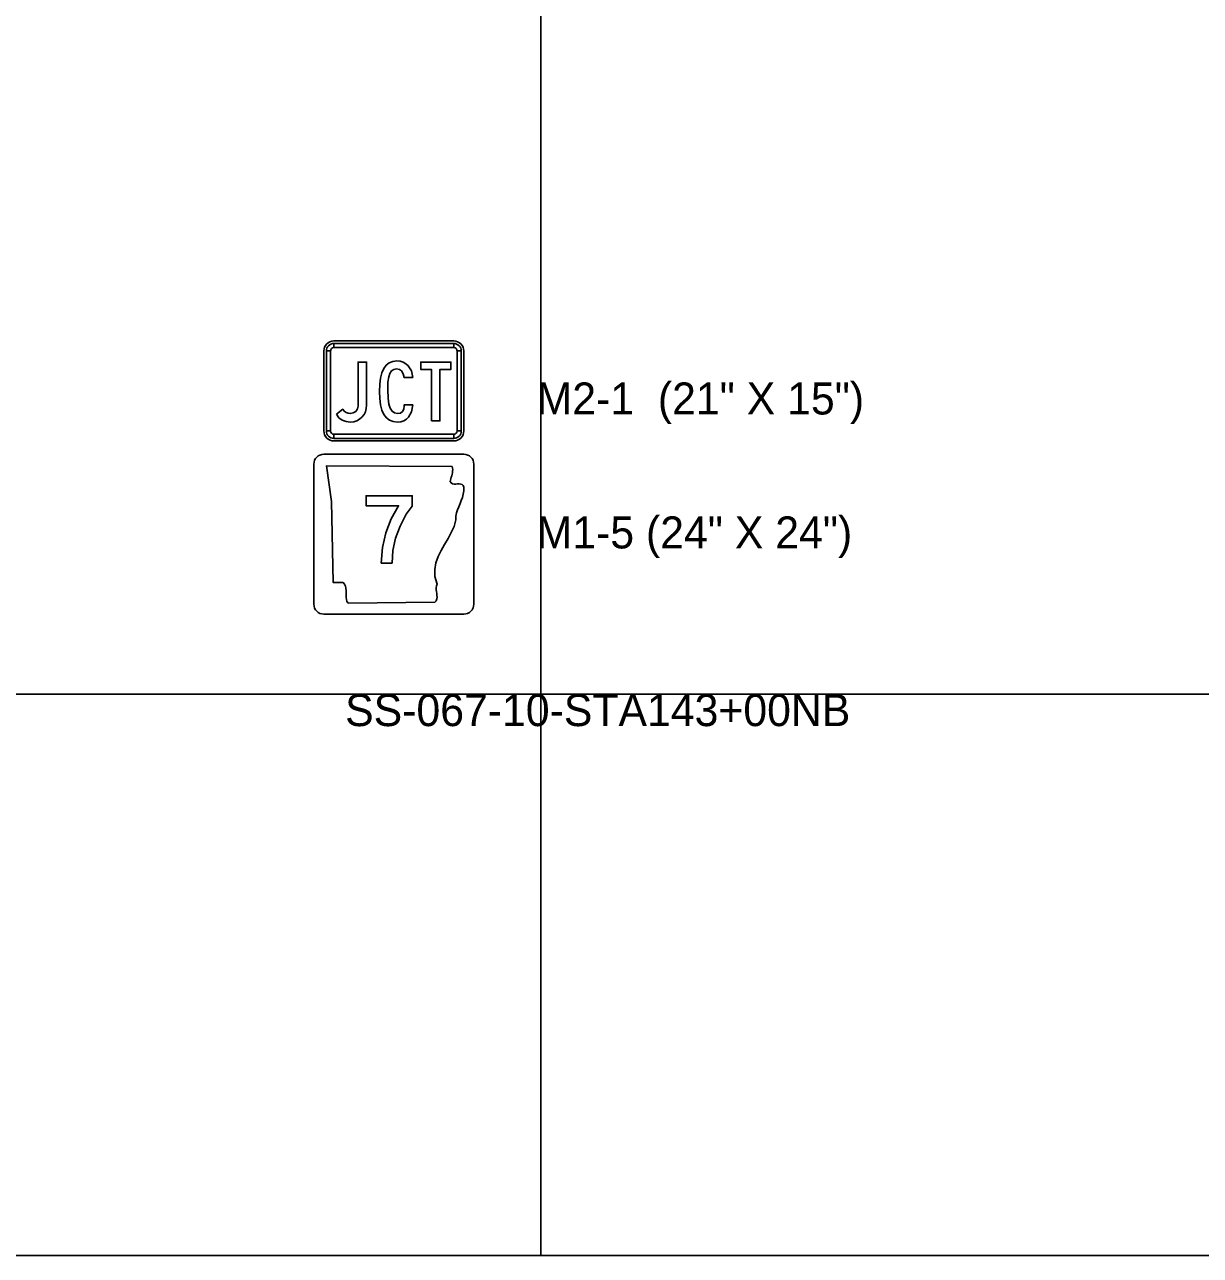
# Model space of a CAD drawing. Extents: x 1001568 to 1002149, y 1840825 to 1841423.
# Drawn here: x 1001929.19 to 1001943.9, y 1841248.13 to 1841263.52 of the extents above; entities that cross this region are included whole.
import ezdxf

# ---------------------------------------------------------------- set-up
doc = ezdxf.new("R2010")
doc.units = 0
for name, color, linetype in [('40', 7, 'Continuous'), ('R_No Plot', 7, 'Continuous'), ('SIGNS', 7, 'Continuous')]:
    doc.layers.add(name, color=color, linetype=linetype)

msp = doc.modelspace()

# ---------------------------------------------------------------- linework, layer by layer
at = {"layer": 'R_No Plot'}
for p, q in [((1001935.65, 1841310.667), (1001935.65, 1841248.127)), ((1001890.65, 1841255.146), (1001982.133, 1841255.146))]:
    msp.add_line(p, q, dxfattribs=at)
msp.add_lwpolyline([(1001886.411, 1841310.667), (1001964.232, 1841310.667), (1001964.232, 1841307.694), (1001968.454, 1841307.694), (1001968.454, 1841306.882), (1001982.133, 1841306.882), (1001982.133, 1841248.127), (1001886.411, 1841248.127)], close=True, dxfattribs=at)
at = {"layer": 'SIGNS'}
for p, q in [((1001933.06, 1841259.562), (1001934.56, 1841259.562)), ((1001933.06, 1841259.479), (1001933.06, 1841259.531)), ((1001934.56, 1841259.531), (1001934.56, 1841259.479)), ((1001932.935, 1841258.437), (1001932.935, 1841259.437)), ((1001932.966, 1841259.437), (1001933.018, 1841259.437)), ((1001934.601, 1841259.437), (1001934.654, 1841259.437)), ((1001934.685, 1841259.437), (1001934.685, 1841258.437)), ((1001933.018, 1841258.437), (1001932.966, 1841258.437)), ((1001933.06, 1841258.344), (1001933.06, 1841258.396)), ((1001934.56, 1841258.396), (1001934.56, 1841258.344)), ((1001934.654, 1841258.437), (1001934.601, 1841258.437)), ((1001934.56, 1841258.312), (1001933.06, 1841258.312)), ((1001934.685, 1841258.146), (1001932.935, 1841258.146)), ((1001932.81, 1841258.021), (1001932.81, 1841256.271)), ((1001934.81, 1841256.271), (1001934.81, 1841258.021)), ((1001932.81, 1841256.271), (1001932.81, 1841256.271)), ((1001932.935, 1841256.146), (1001934.685, 1841256.146))]:
    msp.add_line(p, q, dxfattribs=at)
for points in [[(1001934.56, 1841259.531), (1001933.06, 1841259.531), (1001933.06, 1841259.479), (1001934.56, 1841259.479), (1001934.56, 1841259.531), (1001934.56, 1841259.531)], [(1001932.966, 1841259.437), (1001932.966, 1841258.437), (1001933.018, 1841258.437), (1001933.018, 1841259.437), (1001932.966, 1841259.437), (1001932.966, 1841259.437)], [(1001934.047, 1841259.107), (1001934.029, 1841259.188), (1001933.99, 1841259.252), (1001933.961, 1841259.278), (1001933.927, 1841259.297), (1001933.889, 1841259.309), (1001933.846, 1841259.312), (1001933.796, 1841259.306), (1001933.752, 1841259.289), (1001933.715, 1841259.259), (1001933.685, 1841259.217), (1001933.661, 1841259.164), (1001933.645, 1841259.098), (1001933.634, 1841259.021), (1001933.631, 1841258.932), (1001933.635, 1841258.842), (1001933.645, 1841258.764), (1001933.662, 1841258.698), (1001933.687, 1841258.644), (1001933.718, 1841258.602), (1001933.756, 1841258.572), (1001933.801, 1841258.554), (1001933.854, 1841258.548), (1001933.896, 1841258.552), (1001933.934, 1841258.564), (1001933.967, 1841258.583), (1001933.995, 1841258.611), (1001934.031, 1841258.677), (1001934.047, 1841258.762), (1001933.939, 1841258.762), (1001933.94, 1841258.75), (1001933.936, 1841258.711), (1001933.92, 1841258.681), (1001933.894, 1841258.661), (1001933.857, 1841258.655), (1001933.82, 1841258.662), (1001933.789, 1841258.684), (1001933.765, 1841258.72), (1001933.749, 1841258.772), (1001933.738, 1841258.847), (1001933.735, 1841258.952), (1001933.737, 1841259.047), (1001933.746, 1841259.112), (1001933.761, 1841259.156), (1001933.782, 1841259.188), (1001933.81, 1841259.207), (1001933.844, 1841259.213), (1001933.88, 1841259.206), (1001933.908, 1841259.187), (1001933.928, 1841259.153), (1001933.939, 1841259.107)], [(1001934.654, 1841258.437), (1001934.654, 1841259.437), (1001934.601, 1841259.437), (1001934.601, 1841258.437), (1001934.654, 1841258.437), (1001934.654, 1841258.437)], [(1001933.091, 1841258.645), (1001933.122, 1841258.603), (1001933.165, 1841258.573), (1001933.213, 1841258.554), (1001933.266, 1841258.548), (1001933.308, 1841258.552), (1001933.346, 1841258.563), (1001933.38, 1841258.583), (1001933.411, 1841258.61), (1001933.437, 1841258.642), (1001933.455, 1841258.678), (1001933.466, 1841258.717), (1001933.469, 1841258.759), (1001933.469, 1841259.298), (1001933.363, 1841259.298), (1001933.363, 1841258.748), (1001933.355, 1841258.712), (1001933.334, 1841258.682), (1001933.303, 1841258.662), (1001933.266, 1841258.655), (1001933.237, 1841258.658), (1001933.212, 1841258.668), (1001933.19, 1841258.685), (1001933.172, 1841258.708)], [(1001934.28, 1841258.562), (1001934.387, 1841258.562), (1001934.387, 1841259.206), (1001934.524, 1841259.206), (1001934.524, 1841259.298), (1001934.146, 1841259.298), (1001934.146, 1841259.206), (1001934.28, 1841259.206)], [(1001933.06, 1841258.344), (1001934.56, 1841258.344), (1001934.56, 1841258.396), (1001933.06, 1841258.396), (1001933.06, 1841258.344), (1001933.06, 1841258.344)], [(1001934.54, 1841257.991), (1001934.544, 1841257.972), (1001934.546, 1841257.953), (1001934.545, 1841257.934), (1001934.543, 1841257.915), (1001934.539, 1841257.896), (1001934.534, 1841257.877), (1001934.529, 1841257.858), (1001934.523, 1841257.839), (1001934.518, 1841257.821), (1001934.513, 1841257.803), (1001934.527, 1841257.787), (1001934.544, 1841257.777), (1001934.564, 1841257.773), (1001934.585, 1841257.773), (1001934.606, 1841257.774), (1001934.627, 1841257.774), (1001934.646, 1841257.772), (1001934.663, 1841257.766), (1001934.676, 1841257.754), (1001934.684, 1841257.733), (1001934.685, 1841257.688), (1001934.679, 1841257.645), (1001934.668, 1841257.605), (1001934.654, 1841257.566), (1001934.638, 1841257.528), (1001934.622, 1841257.49), (1001934.607, 1841257.452), (1001934.595, 1841257.412), (1001934.587, 1841257.371), (1001934.585, 1841257.327), (1001934.563, 1841257.244), (1001934.529, 1841257.166), (1001934.488, 1841257.091), (1001934.444, 1841257.016), (1001934.401, 1841256.941), (1001934.363, 1841256.865), (1001934.335, 1841256.787), (1001934.321, 1841256.704), (1001934.324, 1841256.617), (1001934.35, 1841256.523), (1001934.342, 1841256.5), (1001934.34, 1841256.476), (1001934.34, 1841256.452), (1001934.343, 1841256.428), (1001934.347, 1841256.404), (1001934.349, 1841256.381), (1001934.35, 1841256.357), (1001934.347, 1841256.336), (1001934.338, 1841256.314), (1001934.323, 1841256.295), (1001933.239, 1841256.285), (1001933.224, 1841256.305), (1001933.216, 1841256.328), (1001933.212, 1841256.355), (1001933.212, 1841256.383), (1001933.213, 1841256.413), (1001933.213, 1841256.442), (1001933.211, 1841256.471), (1001933.205, 1841256.498), (1001933.194, 1841256.522), (1001933.176, 1841256.543), (1001933.05, 1841256.543), (1001933.032, 1841257.555), (1001932.968, 1841258.001), (1001934.54, 1841257.991), (1001934.54, 1841257.991)], [(1001933.652, 1841256.785), (1001933.788, 1841256.785), (1001933.799, 1841256.944), (1001933.832, 1841257.098), (1001933.888, 1841257.248), (1001933.965, 1841257.395), (1001934.04, 1841257.495), (1001934.04, 1841257.627), (1001933.463, 1841257.627), (1001933.463, 1841257.501), (1001933.87, 1841257.501), (1001933.776, 1841257.336), (1001933.709, 1841257.162), (1001933.667, 1841256.978)]]:
    msp.add_lwpolyline(points, close=True, dxfattribs=at)
for points in [[(1001932.935, 1841258.146), (1001932.935, 1841258.146)], [(1001934.685, 1841258.146), (1001934.685, 1841258.146)], [(1001932.81, 1841258.021), (1001932.81, 1841258.021)], [(1001932.935, 1841256.146), (1001932.935, 1841256.146)], [(1001934.685, 1841256.146), (1001934.685, 1841256.146)]]:
    msp.add_lwpolyline(points, dxfattribs=at)
for centre, radius, start, end in [((1001933.06, 1841259.437), 0.125, 90.0002, 179.9998), ((1001933.06, 1841259.437), 0.0937, 90.0002, 179.9998), ((1001933.06, 1841259.437), 0.0417, 90.0002, 179.9998), ((1001934.56, 1841259.437), 0.125, 360, 90.0002), ((1001934.56, 1841259.437), 0.0937, 360, 90.0002), ((1001934.56, 1841259.437), 0.0417, 360, 90.0002), ((1001933.06, 1841258.437), 0.125, 179.9998, 270.0001), ((1001933.06, 1841258.437), 0.0937, 179.9998, 270.0001), ((1001933.06, 1841258.437), 0.0417, 179.9998, 270.0001), ((1001934.56, 1841258.437), 0.0937, 270.0001, 0.0003), ((1001934.56, 1841258.437), 0.0417, 270.0001, 0.0003), ((1001934.56, 1841258.437), 0.125, 270.0001, 0.0003), ((1001932.935, 1841258.021), 0.125, 90.0002, 179.9998), ((1001934.685, 1841258.021), 0.125, 0, 90), ((1001932.935, 1841256.271), 0.125, 180, 270), ((1001934.685, 1841256.271), 0.125, 270.0001, 0.0003)]:
    msp.add_arc(centre, radius, start, end, dxfattribs=at)

# ---------------------------------------------------------------- texts
at = {"layer": '40'}
for s, p in [('M2-1  (21" X 15")', (1001935.596, 1841258.643)), ('M1-5 (24" X 24")', (1001935.596, 1841256.968)), ('SS-067-10-STA143+00NB', (1001933.201, 1841254.746))]:
    msp.add_text(s, height=0.4, rotation=0, dxfattribs=at).set_placement(p)

doc.saveas('drawing.dxf')
